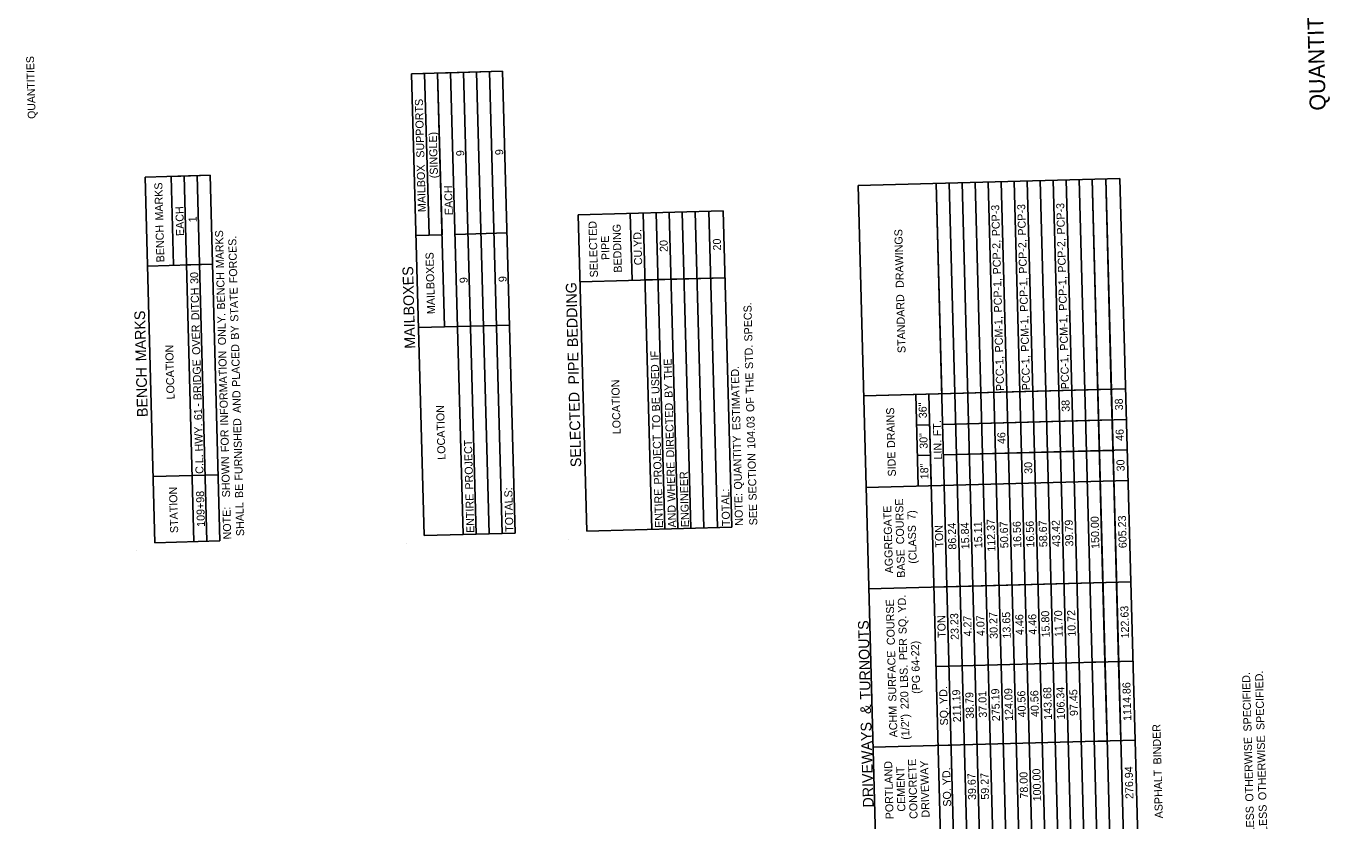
# Model space of a CAD drawing. Extents: x 1930093 to 1931323, y 596452 to 607874.
# Drawn here: x 1930287 to 1931265, y 600068 to 600664 of the extents above; entities that cross this region are included whole.
import ezdxf

# ---------------------------------------------------------------- set-up
doc = ezdxf.new("R2010")
doc.units = 0
for name, color, linetype in [('Default', 7, 'Continuous'), ('R_Border', 7, 'Continuous'), ('R_Border Prem', 7, 'Continuous')]:
    doc.layers.add(name, color=color, linetype=linetype)

msp = doc.modelspace()

# ---------------------------------------------------------------- linework, layer by layer
at = {"layer": 'Default'}
for p, q in [((1930644.65, 600630.36), (1930576.42, 600628.53)), ((1930586.17, 600628.79), (1930576.42, 600628.53)), ((1930585.73, 600282.04), (1930576.42, 600628.53)), ((1930589.43, 600507.45), (1930586.17, 600628.79)), ((1930644.65, 600630.36), (1930595.92, 600629.05)), ((1930601.03, 600438.51), (1930595.92, 600629.05)), ((1930599.17, 600507.71), (1930595.92, 600629.05)), ((1930614.96, 600282.83), (1930605.66, 600629.31)), ((1930624.71, 600283.09), (1930615.41, 600629.58)), ((1930634.46, 600283.35), (1930625.16, 600629.84)), ((1930644.2, 600283.61), (1930634.9, 600630.1)), ((1930653.95, 600283.87), (1930644.65, 600630.36)), ((1930425.27, 600552.3), (1930376.54, 600550.99)), ((1930383.91, 600276.62), (1930376.54, 600550.99)), ((1930425.27, 600552.3), (1930396.03, 600551.51)), ((1930397.83, 600484.75), (1930396.03, 600551.51)), ((1930413.15, 600277.41), (1930405.78, 600551.77)), ((1930422.89, 600277.67), (1930415.53, 600552.03)), ((1930432.64, 600277.93), (1930425.27, 600552.3)), ((1931107.61, 600549.88), (1930911.22, 600544.61)), ((1931107.61, 600549.88), (1930911.22, 600544.61)), ((1931128.83, 599759.44), (1931107.61, 600549.88)), ((1930932.44, 599754.16), (1930911.22, 600544.61)), ((1930990.92, 599755.73), (1930969.7, 600546.17)), ((1930973.94, 600388.28), (1930969.7, 600546.17)), ((1931000.67, 599756), (1930979.45, 600546.44)), ((1931010.41, 599756.26), (1930989.19, 600546.7)), ((1931020.16, 599756.52), (1930998.94, 600546.96)), ((1931029.9, 599756.78), (1931008.69, 600547.22)), ((1931039.65, 599757.04), (1931018.43, 600547.48)), ((1931049.4, 599757.3), (1931028.18, 600547.74)), ((1931059.14, 599757.57), (1931037.93, 600548.01)), ((1931068.89, 599757.83), (1931047.67, 600548.27)), ((1931078.64, 599758.09), (1931057.42, 600548.53)), ((1931088.38, 599758.35), (1931067.17, 600548.79)), ((1931098.13, 599758.61), (1931076.91, 600549.05)), ((1931107.88, 599758.87), (1931086.66, 600549.31)), ((1931096.38, 600187.23), (1931086.66, 600549.31)), ((1931118.11, 599759.15), (1931096.89, 600549.59)), ((1931101.13, 600391.7), (1931096.89, 600549.59)), ((1930810.06, 600525.56), (1930701.39, 600522.64)), ((1930810.06, 600525.56), (1930701.39, 600522.64)), ((1930707.76, 600285.32), (1930701.39, 600522.64)), ((1930741.72, 600473.5), (1930740.38, 600523.69)), ((1930756.49, 600286.63), (1930750.12, 600523.95)), ((1930766.24, 600286.89), (1930759.87, 600524.21)), ((1930775.99, 600287.15), (1930769.62, 600524.48)), ((1930785.73, 600287.41), (1930779.36, 600524.74)), ((1930795.48, 600287.67), (1930789.11, 600525)), ((1930805.71, 600287.95), (1930799.34, 600525.27)), ((1930816.44, 600288.23), (1930810.06, 600525.56)), ((1930599.17, 600507.71), (1930579.68, 600507.19)), ((1930647.91, 600509.02), (1930608.92, 600507.97)), ((1930647.91, 600509.02), (1930608.92, 600507.97)), ((1930427.07, 600485.53), (1930378.33, 600484.22)), ((1930427.07, 600485.53), (1930407.57, 600485.01)), ((1930811.41, 600475.37), (1930702.74, 600472.45)), ((1930811.41, 600475.37), (1930751.47, 600473.76)), ((1930649.76, 600439.82), (1930581.54, 600437.99)), ((1930649.76, 600439.82), (1930610.78, 600438.77)), ((1931111.85, 600391.98), (1930915.46, 600386.71)), ((1931101.13, 600391.7), (1930915.46, 600386.71)), ((1930956.29, 600319.05), (1930954.45, 600387.76)), ((1930974.29, 600011.81), (1930964.19, 600388.02)), ((1930966.04, 600319.31), (1930964.19, 600388.02)), ((1931102.97, 600322.98), (1931101.13, 600391.7)), ((1930964.81, 600365.12), (1930955.06, 600364.85)), ((1930964.81, 600365.12), (1930955.06, 600364.85)), ((1931112.47, 600369.08), (1930974.55, 600365.38)), ((1931101.75, 600368.79), (1930974.55, 600365.38)), ((1931113.08, 600346.18), (1930975.17, 600342.47)), ((1931102.36, 600345.89), (1930975.17, 600342.47)), ((1930965.42, 600342.21), (1930955.68, 600341.95)), ((1930965.42, 600342.21), (1930955.68, 600341.95)), ((1930431.3, 600327.64), (1930382.57, 600326.33)), ((1931113.7, 600323.27), (1930917.3, 600318)), ((1931106.61, 600187.51), (1931102.97, 600322.98)), ((1930816.44, 600288.23), (1930707.76, 600285.32)), ((1930816.44, 600288.23), (1930707.76, 600285.32)), ((1930432.64, 600277.93), (1930383.91, 600276.62)), ((1930432.64, 600277.93), (1930383.91, 600276.62)), ((1930653.95, 600283.87), (1930585.73, 600282.04)), ((1930653.95, 600283.87), (1930585.73, 600282.04)), ((1931115.74, 600247.25), (1930919.35, 600241.98)), ((1931115.74, 600247.25), (1930968.08, 600243.28)), ((1931117.33, 600187.8), (1930969.67, 600183.83)), ((1931096.38, 600187.23), (1931086.63, 600186.97)), ((1931097.97, 600127.78), (1931096.38, 600187.23)), ((1931108.21, 600128.05), (1931106.61, 600187.51)), ((1931118.93, 600128.34), (1930922.54, 600123.07)), ((1930981.02, 600124.64), (1930971.27, 600124.38)), ((1931097.97, 600127.78), (1931088.23, 600127.52))]:
    msp.add_line(p, q, dxfattribs=at)
at = {"layer": 'R_Border'}
for p, q in [((1930694.27, 600279.1), (1930694.27, 600279.1)), ((1930370.42, 600270.41), (1930370.42, 600270.41)), ((1930572.24, 600275.83), (1930572.24, 600275.83))]:
    msp.add_line(p, q, dxfattribs=at)

# ---------------------------------------------------------------- texts
at = {"layer": 'Default'}
for s, height, p in [(' SUPPORTS', 6, (1930586.05, 600563.37)), ('(SINGLE)', 6, (1930596.16, 600550.16)), ('9', 6, (1930615.9, 600566.73)), ('9', 6, (1930645.14, 600567.52)), ('MAILBOX', 6, (1930587.09, 600524.74)), (' MARKS', 6, (1930390.23, 600516.2)), ('EACH', 6, (1930607.33, 600522.46)), (' PCP-3', 6, (1931037.21, 600504.92)), (' PCP-3', 6, (1931066.45, 600505.71)), ('EACH', 6, (1930405.79, 600506.81)), ('1', 6, (1930415.27, 600517.06)), (' PCP-3', 6, (1931017.71, 600504.4)), ('BENCH', 6, (1930391.01, 600487.05)), (' MARKS', 6, (1930435.76, 600480.37)), ('SELECTED', 6, (1930716.15, 600475.76)), ('BEDDING', 6, (1930734.07, 600479.32)), ('CU.YD.', 6, (1930749.3, 600484.89)), (' DRAWINGS', 6, (1930945.6, 600465.59)), (' FORCES.', 6, (1930445.81, 600469.14)), ('PIPE', 6, (1930724.81, 600488.81)), ('20', 6, (1930768.54, 600494.87)), ('20', 6, (1930808.5, 600495.95)), (' PCP-2,', 6, (1931018.48, 600475.81)), (' PCP-2,', 6, (1931037.97, 600476.33)), (' PCP-2,', 6, (1931067.21, 600477.12)), ('MAILBOXES', 6, (1930594.02, 600448.22)), ('MAILBOXES', 8, (1930579.14, 600422.27)), (' 30', 6, (1930416.57, 600468.62)), (' BENCH', 6, (1930436.59, 600449.38)), ('9', 6, (1930618.45, 600471.46)), ('9', 6, (1930647.69, 600472.25)), (' PCP-1,', 6, (1931019.25, 600447.22)), (' PCP-1,', 6, (1931038.74, 600447.74)), (' PCP-1,', 6, (1931067.98, 600448.53)), (' DITCH', 6, (1930417.3, 600441.36)), (' STATE', 6, (1930446.59, 600440.25)), (' BEDDING', 8, (1930701.31, 600420.46)), ('STANDARD', 6, (1930946.86, 600418.98)), (' SPECS.', 6, (1930832.03, 600425.42)), (' MARKS', 8, (1930377.5, 600409.85)), (' ONLY.', 6, (1930437.31, 600422.64)), (' PCM-1,', 6, (1931020.05, 600417.24)), (' PCM-1,', 6, (1931039.55, 600417.76)), (' PCM-1,', 6, (1931068.79, 600418.55)), (' OVER', 6, (1930417.99, 600415.4)), (' BY', 6, (1930446.95, 600426.8)), ('LOCATION', 6, (1930398.65, 600384.2)), (' PLACED', 6, (1930447.9, 600391.39)), (' STD.', 6, (1930832.59, 600404.74)), (' BRIDGE', 6, (1930418.91, 600381.39)), (' INFORMATION', 6, (1930438.93, 600362.34)), (' PIPE', 8, (1930702.06, 600392.45)), (' IF', 6, (1930761.7, 600411.21)), (' THE', 6, (1930771.85, 600396.58)), ('PCC-1,', 6, (1931020.77, 600390.51)), ('PCC-1,', 6, (1931040.26, 600391.04)), ('PCC-1,', 6, (1931069.5, 600391.82)), ('BENCH', 8, (1930378.55, 600370.98)), (' USED', 6, (1930762.38, 600386.04)), (' ESTIMATED.', 6, (1930823.09, 600358.95)), (' THE', 6, (1930833.09, 600386.09)), ('LOCATION', 6, (1930733.19, 600358.07)), (' BY', 6, (1930772.21, 600383.13)), (' AND', 6, (1930448.43, 600371.81)), ('SELECTED', 8, (1930703.65, 600333.39)), (' BE', 6, (1930762.73, 600372.98)), (' OF', 6, (1930833.45, 600372.51)), ('38', 6, (1931109.92, 600376)), (' 61', 6, (1930419.31, 600366.43)), (' -', 6, (1930419.04, 600376.53)), ('LOCATION', 6, (1930601.83, 600338.94)), (' DIRECTED', 6, (1930773.41, 600338.41)), (' DRAINS', 6, (1930939.07, 600345.51)), ('36"', 6, (1930962.8, 600370.08)), ('38', 6, (1931069.96, 600374.92)), (' HWY.', 6, (1930419.94, 600342.95)), (' FURNISHED', 6, (1930449.79, 600321.04)), (' TO', 6, (1930763.09, 600359.39)), (' 104.03', 6, (1930834.19, 600344.95)), (' FT.', 6, (1930973.65, 600354.36)), (' FOR', 6, (1930439.46, 600342.43)), (' PROJECT', 6, (1930764.2, 600318.12)), (' QUANTITY', 6, (1930824.29, 600314.32)), ('30"', 6, (1930963.41, 600347.18)), ('46', 6, (1931021.84, 600350.71)), ('46', 6, (1931110.53, 600353.05)), (' PROJECT', 6, (1930622.67, 600314.32)), ('SIDE', 6, (1930939.59, 600326.36)), ('LIN.', 6, (1930974.06, 600339.11)), ('C.L.', 6, (1930420.33, 600328.32)), ('   SHOWN', 6, (1930440.49, 600304.01)), (' WHERE', 6, (1930774.3, 600305.34)), (' SECTION', 6, (1930835.24, 600306.05)), ('18"', 6, (1930964.03, 600324.27)), ('30', 6, (1931041.95, 600328.35)), ('30', 6, (1931111.15, 600330.21)), ('ENGINEER', 6, (1930784.51, 600288.35)), ('STATION', 6, (1930401.34, 600283.9)), ('109+98', 6, (1930421.4, 600288.59)), (' BE', 6, (1930450.14, 600307.98)), ('TOTALS:', 6, (1930652.73, 600284.82)), ('ENTIRE', 6, (1930765.01, 600287.83)), ('TOTAL:', 6, (1930815.21, 600289.18)), (' SHALL', 6, (1930450.91, 600279.4)), ('ENTIRE', 6, (1930623.49, 600284.03)), ('NOTE:', 6, (1930824.96, 600289.44)), ('SEE', 6, (1930835.68, 600289.73)), (' COURSE', 6, (1930945.89, 600273.27)), ('NOTE:', 6, (1930441.16, 600279.14)), ('AND', 6, (1930774.76, 600288.09)), ('AGGREGATE', 6, (1930937.41, 600253.68)), (' 7)', 6, (1930954.4, 600291.69)), ('150.00', 6, (1931092.23, 600272.04)), ('605.23', 6, (1931112.69, 600272.57)), ('(CLASS', 6, (1930955.23, 600260.9)), ('TON', 6, (1930975.16, 600273)), ('86.24', 6, (1930984.95, 600271.49)), ('15.84', 6, (1930994.7, 600271.75)), ('15.11', 6, (1931004.43, 600272.58)), ('112.37', 6, (1931014.25, 600269.93)), ('50.67', 6, (1931023.94, 600272.53)), ('16.56', 6, (1931033.68, 600272.79)), ('16.56', 6, (1931043.43, 600273.05)), ('58.67', 6, (1931053.18, 600273.31)), ('43.42', 6, (1931062.92, 600273.6)), ('39.79', 6, (1931072.67, 600273.83)), ('BASE', 6, (1930946.5, 600250.4)), (' YD.', 6, (1930947.27, 600222)), (' COURSE', 6, (1930938.92, 600197.61)), ('122.63', 6, (1931114.51, 600204.83)), (' TURNOUTS', 8, (1930920.77, 600156.1)), (' SQ.', 6, (1930947.7, 600205.81)), ('TON', 6, (1930976.98, 600205.26)), ('23.23', 6, (1930986.77, 600203.74)), ('4.27', 6, (1930996.45, 600206.33)), ('4.07', 6, (1931006.2, 600206.59)), ('30.27', 6, (1931016.01, 600204.53)), ('13.65', 6, (1931025.76, 600204.76)), ('4.46', 6, (1931035.44, 600207.38)), ('4.46', 6, (1931045.19, 600207.64)), ('15.80', 6, (1931055, 600205.58)), ('11.70', 6, (1931064.74, 600205.85)), ('10.72', 6, (1931074.49, 600206.13)), (' PER', 6, (1930948.22, 600186.29)), (' 64-22)', 6, (1930957.46, 600177.64)), (' SURFACE', 6, (1930940.06, 600155.19)), (' LBS.', 6, (1930948.78, 600165.45)), (' SPECIFIED.', 6, (1931206.37, 600132.77)), (' SPECIFIED.', 6, (1931216.09, 600133.9)), ('(PG', 6, (1930957.85, 600163.25)), ('1114.86', 6, (1931116.17, 600143.01)), (' 220', 6, (1930949.21, 600149.56)), (' YD.', 6, (1930978.37, 600153.39)), ('211.19', 6, (1930988.43, 600141.95)), ('38.79', 6, (1930998.11, 600144.54)), ('37.01', 6, (1931007.84, 600145.39)), ('275.19', 6, (1931017.67, 600142.74)), ('124.09', 6, (1931027.41, 600143)), ('40.56', 6, (1931037.1, 600145.6)), ('40.56', 6, (1931046.85, 600145.86)), ('143.68', 6, (1931056.65, 600143.78)), ('106.34', 6, (1931066.4, 600144.06)), ('97.45', 6, (1931076.09, 600146.62)), (' &', 8, (1930921.07, 600145.11)), ('ACHM', 6, (1930940.72, 600130.65)), ('SQ.', 6, (1930978.74, 600139.52)), ('DRIVEWAYS', 8, (1930922.87, 600077.98)), ('(1/2")', 6, (1930949.77, 600128.8)), (' BINDER', 6, (1931138.76, 600108.06)), (' OTHERWISE', 6, (1931207.78, 600080.14)), (' OTHERWISE', 6, (1931217.5, 600081.27)), ('PORTLAND', 6, (1930937.86, 600069.18)), ('CONCRETE', 6, (1930955.86, 600069.43)), ('DRIVEWAY', 6, (1930964.84, 600070.39)), ('CEMENT', 6, (1930946.71, 600074.89)), (' YD.', 6, (1930980.68, 600092.49)), ('39.67', 6, (1930999.75, 600083.63)), ('59.27', 6, (1931009.49, 600083.89)), ('78.00', 6, (1931038.73, 600084.69)), ('100.00', 6, (1931048.54, 600082.62)), ('276.94', 6, (1931117.75, 600084.38)), ('  ASPHALT', 6, (1931139.9, 600065.38)), ('SQ.', 6, (1930981.05, 600078.63)), (' UNLESS', 6, (1931208.73, 600044.72)), (' UNLESS', 6, (1931218.45, 600045.84))]:
    msp.add_text(s, height=height, rotation=91.53769, dxfattribs=at).set_placement(p)
at = {"layer": 'R_Border'}
msp.add_text('QUANTITIES', height=12, rotation=91.53769, dxfattribs=at).set_placement((1931261.97, 600601))
at = {"layer": 'R_Border Prem'}
msp.add_text('QUANTITIES', height=5.862, rotation=91.53769, dxfattribs=at).set_placement((1930294.42, 600594.75))

doc.saveas('drawing.dxf')
